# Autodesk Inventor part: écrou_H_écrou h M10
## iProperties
Shininess: 64.0
Length Units: 11269
Angle Units: 11279
Time Units: 11290
Mass Units: 11283
Length Display Precision: 3
Angle Display Precision: 2
Compacted: True
Part Number: écrou_H_écrou h M10
Document SubType Name: Modeling
Created: 2006-01
Material: Par défaut
Designer: riri
Density: 0.0
Volumn: 0.0
Area: 0.0
PropertySet Name: Model Information
Control State: 0
Master: False
Checked Out: False
Author: riri
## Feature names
1. Base1
